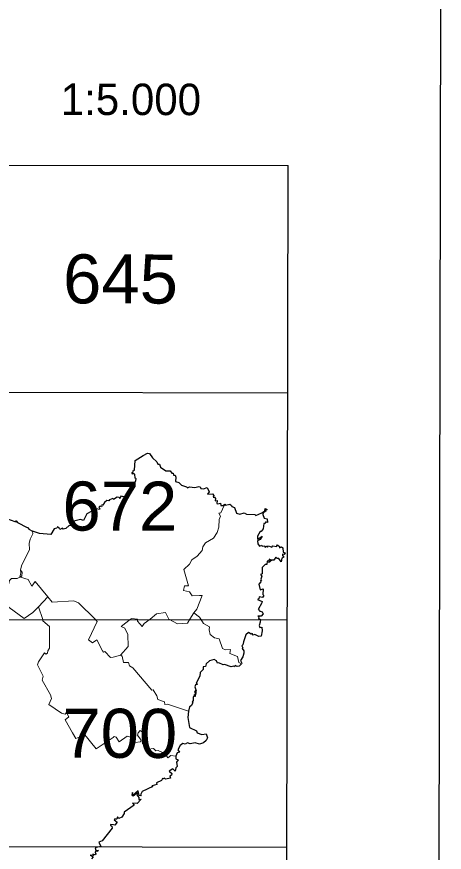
# Model space of a CAD drawing. Extents: x 483855 to 488461, y 4388206 to 4391419.
# Drawn here: x 488290.9 to 488460.8, y 4390273.8 to 4390606 of the extents above; entities that cross this region are included whole.
import ezdxf
from ezdxf.enums import TextEntityAlignment as Align

# ---------------------------------------------------------------- set-up
doc = ezdxf.new("R2010")
doc.units = 0
doc.header["$LTSCALE"] = 4
doc.linetypes.add('DOTTED', pattern=[1.5, 0.3, -1.2])
for name, color, linetype, lineweight in [('1', 7, 'Continuous', 13), ('2', 7, 'DOTTED', 13), ('3', 7, 'Continuous', 25)]:
    doc.layers.add(name, color=color, linetype=linetype, lineweight=lineweight)

msp = doc.modelspace()

# ---------------------------------------------------------------- linework, layer by layer
at = {"layer": '1', "lineweight": 25}
for p, q in [((487983.15, 4390547.59), (488398.83, 4390546.8)), ((488397.97, 4390095.17), (488398.83, 4390546.81)), ((487982.98, 4390457.26), (488398.66, 4390456.47)), ((487844.25, 4390367.21), (488398.49, 4390366.15)), ((487844.08, 4390276.88), (488398.31, 4390275.82))]:
    msp.add_line(p, q, dxfattribs=at)
msp.add_lwpolyline([(483860.86, 4391419.44), (488460.85, 4391410.69), (488454.76, 4388205.69), (483854.77, 4388214.44)], close=True, dxfattribs=at)
at = {"layer": '3'}
for p, q in [((488372.07, 4390411.68), (488372.78, 4390411.68)), ((488372.78, 4390411.68), (488373.57, 4390412.15)), ((488373.57, 4390412.15), (488373.34, 4390411.68))]:
    msp.add_line(p, q, dxfattribs=at)
at = {"layer": '3', "lineweight": 13}
msp.add_line((488361.37, 4390368.97), (488359.77, 4390366.49), dxfattribs=at)
at = {"layer": '3'}
for points in [[(488338.02, 4390422.56), (488337.82, 4390424.19), (488337.13, 4390424.43), (488337.02, 4390424.07), (488336.69, 4390424.79), (488337.07, 4390424.77), (488337.34, 4390425.74), (488337.75, 4390425.67), (488337.95, 4390429.54), (488341.23, 4390431.57)], [(488341.23, 4390431.57), (488342.84, 4390432.44), (488343.76, 4390432.32), (488344.9, 4390430.56), (488346.63, 4390429.04), (488347.01, 4390428.12), (488347.61, 4390428.08), (488348.08, 4390426.85), (488350.24, 4390425.51), (488351.89, 4390425.49), (488352.58, 4390424.53), (488353.12, 4390424.56), (488353.23, 4390423.7)], [(488353.23, 4390423.7), (488353.84, 4390423.7), (488354.11, 4390423), (488354.06, 4390421.2), (488355.3, 4390420.88), (488356.37, 4390419.7), (488358.39, 4390419.16), (488358.79, 4390418.64), (488359.6, 4390419.15), (488361.75, 4390418.8), (488363.35, 4390419.26), (488363.83, 4390419.12), (488364.05, 4390418.41), (488365.22, 4390418.26)], [(488329.14, 4390414.4), (488329.43, 4390414.25), (488330.83, 4390415.12), (488331.57, 4390415.02), (488331.91, 4390414.52), (488332.52, 4390415.57), (488333.14, 4390415.23), (488333.99, 4390415.43), (488334.61, 4390416.33), (488335.62, 4390416.64), (488336.29, 4390417.46), (488336.04, 4390419.14), (488337.51, 4390419.93), (488338.28, 4390421.65), (488338.38, 4390422.28), (488338.02, 4390422.56)], [(488365.22, 4390418.26), (488366.6, 4390418.81), (488367.35, 4390417.06), (488366.81, 4390416.12), (488368.79, 4390416.26), (488369.28, 4390415.59), (488369.02, 4390414.98), (488369.49, 4390415.05), (488369.99, 4390414.47), (488369.76, 4390413.49), (488370.55, 4390413.63), (488370.49, 4390412.53), (488370.8, 4390412.4), (488371.88, 4390412.65), (488372.07, 4390411.68)], [(488329.14, 4390414.4), (488327.75, 4390413.98), (488327.59, 4390413.59), (488326.7, 4390413.66), (488325.77, 4390412.88), (488325.21, 4390411.77), (488324.73, 4390411.98), (488324.74, 4390411.57)], [(488279.06, 4390411.55), (488281.03, 4390410.19), (488281.94, 4390410.32), (488282.23, 4390409.93), (488282.78, 4390410.21), (488283.06, 4390409.59), (488284.41, 4390409.22), (488284.81, 4390408.39), (488285.55, 4390408.15), (488287.24, 4390406.38), (488290.16, 4390405.37), (488290.73, 4390405.24), (488290.42, 4390405.55), (488290.69, 4390405.57), (488291.23, 4390404.95)], [(488324.74, 4390411.57), (488324.58, 4390411.08), (488324.15, 4390411.39), (488323.57, 4390411.08), (488324.02, 4390410.36), (488323.78, 4390410.06), (488322.68, 4390410.39), (488321.86, 4390409.57), (488320.94, 4390409.92), (488320.77, 4390409.41), (488318.8, 4390408.38), (488317.47, 4390405.67), (488316.25, 4390406.04)], [(488373.57, 4390412.15), (488373.88, 4390411.87), (488375.57, 4390412.25), (488376.32, 4390411.7)], [(488376.32, 4390411.7), (488376.44, 4390411.25), (488377.48, 4390410.85), (488378.31, 4390408.58), (488379.58, 4390408.16), (488381.3, 4390408.77), (488382.23, 4390408.24), (488385.61, 4390408.12), (488385.95, 4390407.69), (488388.38, 4390408.77), (488389.48, 4390409.6), (488389.73, 4390410.44), (488390.4, 4390410.13), (488389.85, 4390409.68), (488389.96, 4390409.39)], [(488389.96, 4390409.39), (488388.85, 4390408.78), (488388.76, 4390408.1), (488389.22, 4390406.59), (488390.4, 4390406.33), (488390.57, 4390404.87), (488389.93, 4390405.14), (488389.61, 4390404.51), (488389.13, 4390404.53), (488388.92, 4390402.41), (488388.14, 4390401.35), (488387.67, 4390401.28), (488386.63, 4390399.47), (488386.56, 4390398.28), (488387.18, 4390398.55)], [(488291.23, 4390404.95), (488295.01, 4390402.86), (488295.43, 4390402.95), (488295.73, 4390402.23), (488297.17, 4390401.45)], [(488316.25, 4390406.04), (488313.58, 4390405.42), (488313.84, 4390405.18), (488312.94, 4390403.65), (488311.75, 4390403.7), (488310.44, 4390402.56), (488309.33, 4390402.2), (488309.12, 4390402.71), (488308.06, 4390402.18), (488307.73, 4390402.69)], [(488307.73, 4390402.69), (488307.07, 4390403.21), (488306.85, 4390402.7), (488305.83, 4390402.42), (488304.51, 4390400.08), (488300.04, 4390400.49), (488297.17, 4390401.45)], [(488387.18, 4390398.55), (488388.5, 4390399.43), (488387.72, 4390398.21), (488386.59, 4390397.57), (488386.73, 4390396.45), (488387.39, 4390395.54), (488388.4, 4390395.94), (488388.52, 4390395.45), (488389.45, 4390395.57), (488389.59, 4390395.07), (488390.16, 4390395.48), (488390.57, 4390395.09), (488390.94, 4390395.68), (488392.28, 4390395.11), (488392.77, 4390395.59), (488394.2, 4390395.4), (488394.52, 4390396.03), (488395.43, 4390395.27), (488395.34, 4390394.84), (488396.14, 4390395.27)], [(488396.14, 4390395.27), (488396.62, 4390394.9), (488396.76, 4390393.14), (488397.57, 4390392.89), (488397.25, 4390392.14), (488396.55, 4390392.28), (488396.54, 4390391.73), (488397.13, 4390391.19), (488396.31, 4390390.73), (488396.01, 4390389.33), (488395.14, 4390390.62), (488394.49, 4390390.63), (488393.96, 4390391.17), (488393.15, 4390389.93), (488392.26, 4390389.87), (488391.16, 4390389.07), (488391.33, 4390389.64)], [(488391.33, 4390389.64), (488392.05, 4390389.9), (488391.19, 4390390.28), (488391.15, 4390389.72), (488390.48, 4390389.55), (488390.37, 4390388.27), (488389.71, 4390388.23), (488388.52, 4390387.08), (488388.41, 4390384.49), (488387.8, 4390384.26), (488388.34, 4390383.53), (488387.92, 4390382.35), (488388.22, 4390381.89), (488387.79, 4390381.89), (488387.9, 4390381.28), (488387.14, 4390380.43)], [(488387.14, 4390380.43), (488387.71, 4390378.2), (488388.9, 4390378.51), (488388.72, 4390376.32), (488389.08, 4390375.9), (488388.55, 4390375.07), (488387.31, 4390375.31), (488387.1, 4390374.51), (488386.64, 4390374.34), (488388.52, 4390373.56), (488388.4, 4390372.99)], [(488388.4, 4390372.99), (488386.92, 4390370.38), (488387.4, 4390370.08), (488387.3, 4390369.76), (488388.52, 4390369.34), (488388.81, 4390368.62), (488388.01, 4390367.71), (488386.76, 4390367.72), (488387.1, 4390367.47), (488387.01, 4390366.71), (488387.47, 4390366.55)], [(488387.47, 4390366.55), (488387.77, 4390366.32), (488387.73, 4390365.26), (488387.23, 4390364), (488387.52, 4390363.22), (488388.3, 4390363.32), (488388.53, 4390361.85), (488388.02, 4390359.74), (488387.2, 4390359.54), (488385.5, 4390360.42), (488384.93, 4390360.05), (488384.46, 4390360.81), (488384.14, 4390360.56), (488383.09, 4390361.19), (488381.92, 4390360.2), (488380.99, 4390357.51)], [(488380.99, 4390357.51), (488380.84, 4390356.25), (488380.35, 4390355.84), (488380.79, 4390355.09), (488380.46, 4390354.8), (488381.22, 4390353.92), (488381.22, 4390352.94), (488380.83, 4390351.48), (488379.81, 4390350), (488380.39, 4390349.02), (488380.23, 4390348.67)], [(488380.23, 4390348.67), (488379.33, 4390347.73), (488378.53, 4390347.6), (488377.68, 4390348.01), (488377.5, 4390347.52), (488377.16, 4390347.76), (488376.14, 4390347.47), (488373.54, 4390348.47), (488372.96, 4390348.26), (488371.19, 4390349.11), (488370.74, 4390348.92), (488370.32, 4390349.97), (488369.36, 4390350.39), (488367.54, 4390349.89)], [(488367.54, 4390349.89), (488366.21, 4390348.73), (488365.89, 4390347.71), (488365.05, 4390347.58), (488365.02, 4390346.49), (488363.84, 4390345.32), (488363.71, 4390343.82), (488362.19, 4390341.05), (488362.72, 4390340.64), (488361.92, 4390340.4), (488361.77, 4390339.63), (488362.25, 4390337.97), (488361.93, 4390338.14), (488361.61, 4390337.43), (488362.39, 4390337.68), (488362.03, 4390337.25), (488362.22, 4390336.97), (488361.76, 4390336.81), (488362.09, 4390336.28), (488361.37, 4390336.19)], [(488361.37, 4390336.19), (488361.98, 4390335.88), (488361, 4390335.61), (488361.07, 4390334.16), (488360.62, 4390333.43), (488360.86, 4390333.25), (488360.26, 4390332.08), (488359.57, 4390331.6), (488359.23, 4390329.95)], [(488359.23, 4390329.95), (488358.93, 4390327.32), (488359.64, 4390323.36), (488362.36, 4390322.06), (488362.62, 4390321.33)], [(488362.62, 4390321.33), (488364.5, 4390320.63), (488366.22, 4390320.89), (488366.78, 4390319.25), (488366.27, 4390318.22), (488365.15, 4390317.36), (488363.5, 4390316.82), (488361.84, 4390317.35), (488359.92, 4390316.9), (488358.79, 4390317.29), (488357.89, 4390316.75)], [(488357.89, 4390316.75), (488356.93, 4390317.06), (488355.84, 4390316.25), (488354.92, 4390314.46), (488355.57, 4390313.63), (488354.75, 4390313.33), (488354.1, 4390312.03)], [(488354.1, 4390312.03), (488354.19, 4390310.92), (488355.1, 4390310.6), (488354.42, 4390309.58), (488354.73, 4390307.91), (488354.1, 4390307.39), (488353.87, 4390306.05), (488353.03, 4390306.93), (488351.51, 4390306.06), (488352.52, 4390305.14), (488352.43, 4390304.46), (488351.82, 4390304.02), (488352.05, 4390303.25), (488350.01, 4390302.92), (488349.61, 4390303.27), (488349.28, 4390302.98), (488348.83, 4390303.17), (488348.46, 4390302.26), (488346.45, 4390301.4), (488346.6, 4390300.73), (488344.73, 4390300.21), (488344.68, 4390299.92), (488345.06, 4390299.92)], [(488345.06, 4390299.92), (488340.73, 4390297.89), (488340.17, 4390296.67), (488340.44, 4390296.17), (488339.57, 4390296.41), (488339.15, 4390298.25), (488337.3, 4390296.59), (488336.91, 4390296.66), (488336.9, 4390297.57), (488336.72, 4390296.58), (488337.15, 4390296.28), (488338.99, 4390297.52), (488338.62, 4390296.59), (488339.39, 4390295.58), (488339.47, 4390294.75), (488340.37, 4390294.94), (488338.75, 4390293.23), (488336.94, 4390293.32)], [(488336.94, 4390293.32), (488337.6, 4390292.55), (488333.61, 4390289.7), (488333.68, 4390289.22), (488332.75, 4390287.74), (488331.55, 4390287.24), (488331.02, 4390287.82), (488330.66, 4390286.94), (488329.76, 4390286.98), (488329.68, 4390286.65), (488330.79, 4390285.82), (488329.97, 4390284.58), (488329.33, 4390284.76)], [(488329.33, 4390284.76), (488328.2, 4390284.81), (488328.13, 4390284.37), (488328.78, 4390284.14), (488328.91, 4390283.43), (488324.9, 4390278.35), (488323.6, 4390277.74), (488324.41, 4390276.08)], [(488324.41, 4390276.08), (488322.09, 4390275.52), (488322.38, 4390274.67), (488323.48, 4390274.52), (488322.87, 4390274.04), (488322.24, 4390274.33), (488322.04, 4390273.85), (488322.43, 4390273.11), (488322.14, 4390272.77), (488321.19, 4390272.97), (488321.41, 4390272.55), (488320.07, 4390272.67), (488321.28, 4390271.99), (488320.58, 4390271.13)]]:
    msp.add_lwpolyline(points, dxfattribs=at)
at = {"layer": '3', "lineweight": 13}
for points in [[(488373.34, 4390411.68), (488372.11, 4390408.8), (488371.2, 4390408.67), (488371.96, 4390407.45), (488371.36, 4390406.07), (488371.23, 4390403.08), (488370.57, 4390400.89), (488369.19, 4390398.66), (488365.94, 4390396.81), (488364.93, 4390395.23), (488364.63, 4390393.78), (488362.69, 4390391.46), (488360.46, 4390390.11), (488359.62, 4390388.35), (488357.37, 4390386.16), (488359.21, 4390379.77), (488357.59, 4390379.71), (488357.18, 4390377.88), (488359.6, 4390377.36), (488360.65, 4390375.77), (488363.57, 4390375.92)], [(488297.17, 4390401.45), (488297.34, 4390400.38), (488296.26, 4390398.24), (488295.91, 4390396.51), (488295.97, 4390394.18), (488292.83, 4390387.64), (488292.4, 4390385.91)], [(488292.4, 4390385.91), (488292.62, 4390384.84), (488292.1, 4390383.15), (488291.08, 4390382.65), (488288.83, 4390382.61), (488288.1, 4390381.91), (488287.22, 4390378.47), (488287.37, 4390376.04), (488284.46, 4390377.64), (488283.19, 4390379), (488282.54, 4390378.91), (488281.89, 4390381.5), (488281.99, 4390383.56), (488281.66, 4390383.87), (488276.45, 4390381.82), (488272.69, 4390381.33), (488271.78, 4390379.32), (488270.31, 4390378), (488267.85, 4390378.63)], [(488292.4, 4390385.91), (488293.07, 4390385.1), (488292.94, 4390383.67), (488292.37, 4390383.15), (488295.49, 4390382.23), (488296.93, 4390379.66), (488298.27, 4390381.4), (488303.24, 4390375.34)], [(488303.24, 4390375.34), (488299.52, 4390371.38), (488301.33, 4390366.4)], [(488303.24, 4390375.34), (488304.95, 4390373.3), (488313.63, 4390373.71), (488315.47, 4390373.03), (488322.08, 4390366.41)], [(488363.57, 4390375.92), (488364.67, 4390375.87), (488362.52, 4390370.43), (488361.37, 4390368.97)], [(488299.52, 4390371.38), (488297.36, 4390369.15), (488293.82, 4390366.73), (488285.98, 4390372.58), (488284.61, 4390369.3), (488284.2, 4390366.89), (488283.6, 4390366.38)], [(488336.11, 4390366.42), (488336.67, 4390366.73), (488338.96, 4390366.44)], [(488343.95, 4390366.45), (488346.54, 4390368.6), (488350.04, 4390369.19), (488351.33, 4390366.46)], [(488361.37, 4390368.97), (488363.63, 4390367.32), (488364.06, 4390366.5)], [(488301.33, 4390366.4), (488301.35, 4390365.84), (488303.97, 4390363.58), (488304.01, 4390354.96), (488303.24, 4390353.88), (488303.15, 4390353), (488302.53, 4390352.62), (488301.99, 4390353.07), (488299.6, 4390349.55), (488299.19, 4390348.26), (488301.44, 4390343.78), (488301.02, 4390342.19), (488304.35, 4390336.44), (488304.72, 4390334.92), (488303.75, 4390332.57), (488308.7, 4390329.14), (488310.19, 4390328.71), (488310.76, 4390329.37), (488311.64, 4390327.59), (488310.19, 4390326.42), (488313.11, 4390321.24)], [(488322.08, 4390366.41), (488322.92, 4390365.61), (488319.51, 4390358.3), (488321.09, 4390357.02), (488322.82, 4390358.28), (488324.96, 4390353.82), (488325.46, 4390353.41), (488326, 4390353.67), (488328.23, 4390351.2), (488329.23, 4390351.41)], [(488336.11, 4390366.42), (488332.47, 4390363.58), (488333.89, 4390362.92), (488335.05, 4390360.44), (488335.23, 4390355.62), (488332.12, 4390352.12), (488329.23, 4390351.41)], [(488338.96, 4390366.44), (488338.91, 4390365.62), (488340.73, 4390363.6), (488341.57, 4390364.69), (488343.95, 4390366.45)], [(488351.33, 4390366.46), (488354.82, 4390364.64), (488358.77, 4390364.88), (488359.77, 4390366.49)], [(488364.06, 4390366.5), (488365.09, 4390364.74), (488367.52, 4390363.42), (488367.36, 4390362.25), (488367.86, 4390360.37), (488369.59, 4390359.11), (488371.39, 4390358.66), (488372.72, 4390354.79), (488373.9, 4390354.22), (488375.84, 4390354.35), (488375.62, 4390352.82), (488378.68, 4390351.62), (488379.24, 4390349.28), (488380.23, 4390348.67)], [(488332.12, 4390352.12), (488332.78, 4390351.78), (488333.33, 4390349.27), (488335.31, 4390349.22), (488335.74, 4390347.9), (488337.04, 4390347.18), (488344.61, 4390338.21), (488345.12, 4390338.39), (488346.55, 4390335.97), (488346.96, 4390334.49), (488349.59, 4390333.67), (488349.79, 4390332.56), (488350.79, 4390332.63), (488359.23, 4390329.95)], [(488313.11, 4390321.24), (488314.41, 4390318.99), (488317.04, 4390320.15), (488317.44, 4390321.09), (488322.46, 4390314.95), (488329.28, 4390319.47)], [(488339.14, 4390321.28), (488338.95, 4390320.39), (488340.37, 4390318.4), (488340.17, 4390317.71), (488337.88, 4390317.4), (488336.13, 4390319.5), (488334.8, 4390319.91), (488331.59, 4390317.73), (488330.51, 4390319.58), (488329.7, 4390319.77), (488329.28, 4390319.47)], [(488339.14, 4390321.28), (488340.01, 4390322.2), (488341.29, 4390321.28)], [(488341.29, 4390321.28), (488342.31, 4390319), (488340.78, 4390317.99), (488340.95, 4390317.07), (488341.52, 4390316.59), (488342.96, 4390317.4), (488343.31, 4390314.76), (488345.27, 4390315.01), (488346.24, 4390314.1), (488347.19, 4390314.23), (488349.76, 4390313.12), (488350.96, 4390311.37), (488352.18, 4390312.22), (488354.1, 4390312.03)]]:
    msp.add_lwpolyline(points, dxfattribs=at)

# ---------------------------------------------------------------- texts
at = {"layer": '2'}
msp.add_text('1:5.000', height=12.5, rotation=359.891, dxfattribs=at).set_placement((488308.4, 4390566.98))
at = {"layer": '2', "width": 1.05}
for s, p in [('645', (488332.15, 4390492)), ('672', (488331.9, 4390401.67)), ('700', (488331.86, 4390311.34))]:
    msp.add_text(s, height=19.5, rotation=359.891, dxfattribs=at).set_placement(p, align=Align.CENTER)

doc.saveas('drawing.dxf')
